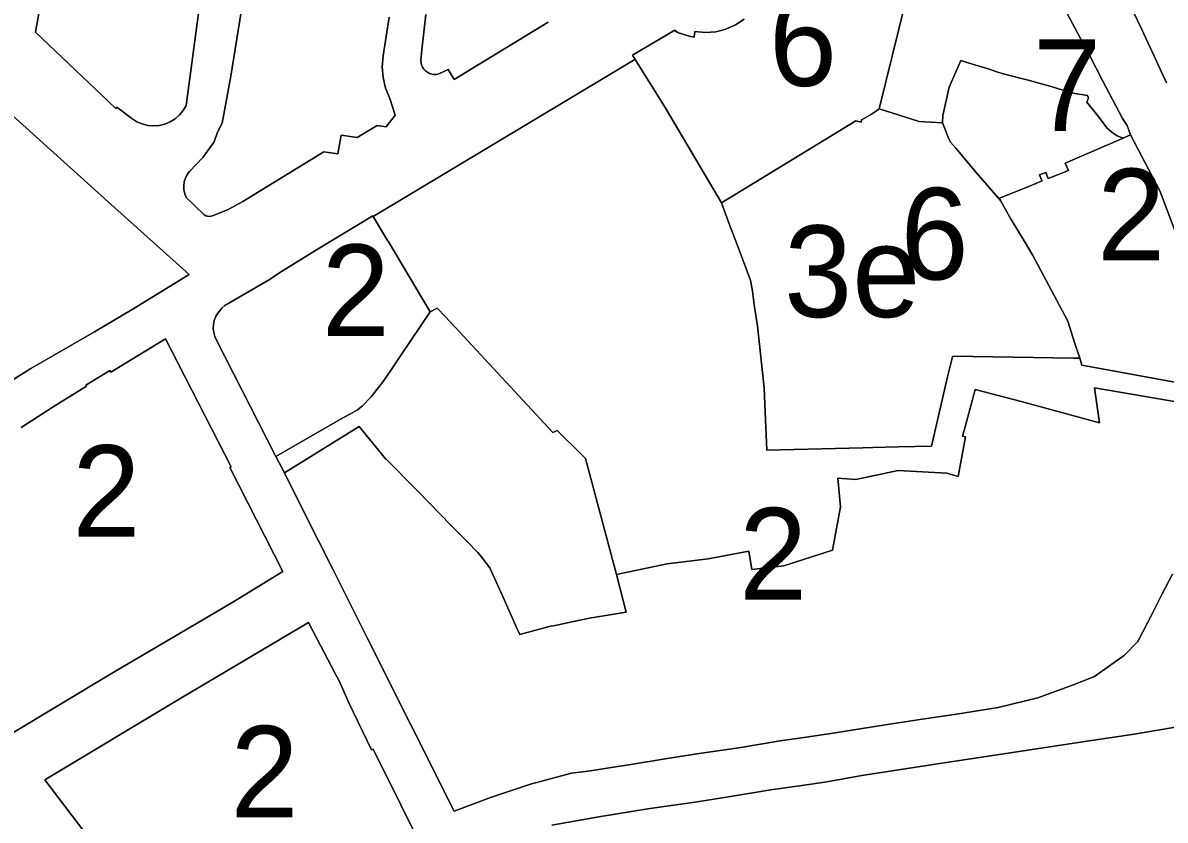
# Model space of a CAD drawing. Extents: x 598968 to 613553, y 4409678 to 4430833.
# Drawn here: x 607565.5 to 607715.2, y 4416375.4 to 4416479.9 of the extents above; entities that cross this region are included whole.
import ezdxf

# ---------------------------------------------------------------- set-up
doc = ezdxf.new("R2010")
doc.units = 0
for name, color, linetype in [('1', 7, 'Continuous'), ('SUBZONA 3e. EDIFICIS ENTRE MITGERES amb projecte especial', 7, 'Continuous'), ('ZONA 2. CARRERS DE CASES. Cases de trast', 7, 'Continuous'), ("ZONA 3. ILLES  D'EDIFICIS ENTRE MITGERES. EIXAMPLE.", 7, 'Continuous'), ('ZONA 6. EDIFICIS DE PISOS_ AÏLLATS I EN PARCEL.LES', 7, 'Continuous'), ('ZONA 7. CONJUNTS AMB ORDENACIONS ESPECÍFIQUES', 7, 'Continuous')]:
    doc.layers.add(name, color=color, linetype=linetype)

msp = doc.modelspace()

# ---------------------------------------------------------------- linework, layer by layer
at = {"layer": '1'}
for points in [[(607579.6918, 4416548.9945), (607584.0576, 4416548.2277), (607597.4675, 4416536.408), (607594.4076, 4416516.8082), (607589.6485, 4416489.6645), (607586.8878, 4416469.0585), (607586.5075, 4416468.4009), (607586.0264, 4416467.813), (607585.4571, 4416467.3101), (607584.8143, 4416466.9053), (607584.1149, 4416466.6092), (607583.3768, 4416466.4294), (607582.6195, 4416466.3705), (607581.8625, 4416466.4343), (607581.1257, 4416466.6189), (607580.4281, 4416466.9196), (607579.7879, 4416467.3284), (607577.8379, 4416468.8084), (607577.6879, 4416468.6584), (607567.168, 4416478.6381)], [(607643.3058, 4416407.559), (607643.2873, 4416407.5551), (607639.2425, 4416422.7691), (607638.7868, 4416423.2214), (607635.5472, 4416426.4367), (607634.9444, 4416426.1964), (607621.5759, 4416440.5814), (607621.5719, 4416440.5857), (607619.898, 4416442.3867), (607619.8075, 4416442.4843), (607618.897, 4416441.9936), (607615.0876, 4416436.3694), (607613.7882, 4416434.3877), (607612.7176, 4416432.8494), (607611.3071, 4416431.0654), (607611.1047, 4416430.8095), (607610.0244, 4416429.6742), (607609.3377, 4416429.1694), (607608.4427, 4416428.6494), (607607.5442, 4416428.1274), (607598.6578, 4416423.0393), (607599.7778, 4416420.9093), (607609.5877, 4416426.9494), (607613.0906, 4416422.6874), (607613.0993, 4416422.6777), (607617.2178, 4416418.5299), (607617.2972, 4416418.4493), (607621.5757, 4416414.0391), (607623.6294, 4416411.9724), (607625.1175, 4416410.4749), (607625.3833, 4416410.1381), (607626.7075, 4416408.4599), (607628.392, 4416404.6996), (607630.2444, 4416400.5217), (607630.6437, 4416399.6873), (607634.6675, 4416400.7902), (607635.0247, 4416400.8648), (607638.4943, 4416401.5887), (607639.9874, 4416401.9003), (607640.2815, 4416401.9484), (607644.5773, 4416402.6503), (607644.5756, 4416402.6569), (607643.2873, 4416407.5502), (607643.307, 4416407.5543)], [(607586.1981, 4416391.3494), (607602.9279, 4416401.2996), (607606.4778, 4416394.4898), (607606.9378, 4416393.6198), (607608.2878, 4416390.6798), (607611.1978, 4416384.58), (607611.4028, 4416384.67), (607615.0278, 4416377.3701), (607617.0677, 4416373.3102), (607613.2778, 4416371.2401), (607608.9179, 4416368.2401), (607604.578, 4416364.4601), (607604.738, 4416364.3401), (607601.618, 4416360.5301), (607601.408, 4416360.6401), (607595.9181, 4416350.1501), (607588.8482, 4416353.9399), (607579.0183, 4416366.6996), (607568.3783, 4416380.6393)]]:
    msp.add_lwpolyline(points, close=True, dxfattribs=at)
for points in [[(607613.5074, 4416480.6189), (607612.7174, 4416475.5589), (607612.6056, 4416474.1282), (607612.7143, 4416472.6973), (607613.0408, 4416471.2999), (607613.5775, 4416469.969), (607614.3075, 4416467.769), (607613.1175, 4416466.249), (607611.9175, 4416466.439), (607609.3176, 4416464.839), (607607.2176, 4416465.1689), (607606.7776, 4416462.689), (607604.9676, 4416462.9689), (607594.3478, 4416456.4488), (607592.4099, 4416455.4029), (607590.3678, 4416454.5788), (607590.1487, 4416454.5247), (607589.9236, 4416454.5087), (607589.699, 4416454.5314), (607589.4817, 4416454.592), (607589.2778, 4416454.6888), (607586.9079, 4416456.9787), (607586.7163, 4416457.4643), (607586.609, 4416457.9753), (607586.5891, 4416458.497), (607586.6571, 4416459.0146), (607586.8113, 4416459.5134), (607587.0471, 4416459.9792), (607587.3578, 4416460.3987), (607589.1122, 4416462.2167), (607590.5578, 4416464.2887), (607591.0277, 4416465.5299), (607591.6178, 4416466.7187), (607592.7577, 4416472.8886), (607595.282, 4416488.6863)], [(607548.7182, 4416481.6777), (607554.1282, 4416476.7379), (607561.4181, 4416470.1181), (607577.118, 4416456.0285), (607587.2779, 4416446.9088), (607579.838, 4416442.2987), (607574.8981, 4416439.3637), (607566.5582, 4416434.5486), (607561.4582, 4416431.3685), (607557.0483, 4416428.7685), (607554.4883, 4416427.3685), (607552.5284, 4416425.9884), (607539.7085, 4416418.2183), (607536.2286, 4416422.7782), (607526.8686, 4416434.8179), (607520.5687, 4416442.8477), (607518.9087, 4416444.9276), (607514.6887, 4416447.4175), (607511.0696, 4416448.9222), (607503.6483, 4416451.9927), (607496.0345, 4416454.9201), (607488.779, 4416458.087), (607477.7191, 4416462.8967)], [(607681.1705, 4416482.5814), (607677.7059, 4416468.596), (607682.9467, 4416466.9301), (607686.0266, 4416466.7603), (607686.0466, 4416467.7303), (607686.8966, 4416471.4303), (607688.4166, 4416474.9302), (607688.4263, 4416474.9273), (607690.0877, 4416474.4336), (607692.0165, 4416473.8603), (607693.1622, 4416473.4393), (607693.972, 4416473.1775), (607697.4065, 4416472.3304), (607698.8166, 4416471.936), (607699.9465, 4416471.6205), (607700.4067, 4416471.479), (607700.9414, 4416471.3255), (607702.9064, 4416470.7105), (607705.0464, 4416470.3306), (607705.1162, 4416470.1465), (607705.1564, 4416470.0406), (607704.9464, 4416469.4706), (607706.0395, 4416468.1186), (607706.3724, 4416467.6926), (607707.6064, 4416466.0807), (607708.2464, 4416465.5107), (607708.9264, 4416465.0807), (607709.7152, 4416464.7612), (607709.7876, 4416464.7933), (607710.6764, 4416465.2007), (607710.2336, 4416466.4073), (607709.6164, 4416467.3407), (607707.0114, 4416472.3156), (607705.2664, 4416475.6405), (607704.1033, 4416477.8153), (607703.3464, 4416479.2304), (607701.4264, 4416482.8204)], [(607701.4264, 4416482.8204), (607703.3464, 4416479.2304), (607704.1033, 4416477.8153), (607705.2664, 4416475.6405), (607707.0114, 4416472.3156), (607709.6164, 4416467.3407), (607710.2336, 4416466.4073), (607710.6764, 4416465.2007), (607714.4963, 4416457.8609), (607714.7278, 4416457.272), (607718.5863, 4416447.1111)], [(607715.38, 4416472.0059), (607713.7999, 4416475.428), (607712.1584, 4416478.9829), (607710.4133, 4416482.6275)], [(607710.4133, 4416482.6275), (607712.1584, 4416478.9829), (607713.7999, 4416475.428), (607715.38, 4416472.0059)], [(607716.1515, 4416407.6265), (607714.8315, 4416405.0215), (607713.5387, 4416402.5053), (607711.6266, 4416398.7815), (607709.8666, 4416396.9915), (607705.9367, 4416394.2215), (607703.0767, 4416393.0865), (607698.5367, 4416391.4214), (607693.3168, 4416390.1213), (607687.8669, 4416389.2812), (607683.3469, 4416388.6112), (607678.2384, 4416387.8405), (607671.3749, 4416386.7354), (607668.1471, 4416386.2559), (607664.7472, 4416385.7509), (607659.3172, 4416384.8708), (607654.1243, 4416384.0988), (607649.9373, 4416383.4406), (607644.9374, 4416382.6406), (607642.3574, 4416382.2405), (607639.9038, 4416381.8601), (607637.3975, 4416381.5204), (607632.0169, 4416380.0902), (607626.9165, 4416378.3742), (607622.0477, 4416376.5602), (607616.3277, 4416387.86), (607610.692, 4416399.0797), (607607.474, 4416405.5786), (607606.1578, 4416408.1896), (607604.2528, 4416411.985), (607602.3379, 4416415.8), (607599.7778, 4416420.9093), (607598.6578, 4416423.0393), (607590.8805, 4416438.266), (607590.6591, 4416438.7562), (607590.5176, 4416439.2751), (607590.4595, 4416439.8098), (607590.4863, 4416440.347), (607590.5973, 4416440.8733), (607590.7898, 4416441.3756), (607591.0589, 4416441.8413), (607591.3979, 4416442.2589), (607591.5654, 4416442.4564), (607591.9878, 4416442.8189), (607597.8978, 4416446.259), (607599.0577, 4416447.049), (607604.1977, 4416450.2491), (607611.3676, 4416454.5891), (607611.4178, 4416454.5042), (607645.7247, 4416475.0641), (607645.7423, 4416475.0719), (607645.3871, 4416475.6395), (607650.957, 4416478.9095), (607651.287, 4416478.6096), (607652.8417, 4416478.1042), (607653.487, 4416477.9996), (607653.567, 4416478.7296), (607654.9379, 4416478.5991), (607656.3111, 4416478.7032), (607657.6466, 4416479.0391), (607658.9059, 4416479.5967), (607660.0521, 4416480.36)], [(607634.3372, 4416479.9592), (607627.7373, 4416475.9492), (607622.0473, 4416472.4391), (607621.2274, 4416473.7591), (607620.0074, 4416473.1791), (607619.7042, 4416473.1214), (607619.3957, 4416473.1149), (607619.0904, 4416473.1596), (607618.7967, 4416473.2543), (607618.5228, 4416473.3964), (607618.2763, 4416473.5821), (607618.064, 4416473.8061), (607617.8918, 4416474.0622), (607617.7645, 4416474.3433), (607617.6857, 4416474.6417), (607617.6574, 4416474.949), (607617.8058, 4416476.3232), (607618.3074, 4416480.9689)], [(607565.2682, 4416426.8487), (607569.4781, 4416429.5287), (607573.8281, 4416432.2587), (607573.7481, 4416432.3987), (607576.888, 4416434.3188), (607577.018, 4416434.0988), (607584.1979, 4416438.4789), (607592.7879, 4416421.6892), (607592.6179, 4416421.5892), (607599.5679, 4416407.9695), (607593.0304, 4416403.9379), (607588.338, 4416401.2094), (607577.1382, 4416394.5892), (607563.7584, 4416386.5391)], [(607634.8075, 4416374.7205), (607641.0075, 4416375.8206), (607647.4274, 4416376.8407), (607653.8673, 4416377.7808), (607658.2273, 4416378.4708), (607663.5472, 4416379.3309), (607667.9071, 4416379.951), (607670.5871, 4416380.341), (607675.727, 4416381.2611), (607686.2269, 4416382.8813), (607699.5068, 4416384.9015), (607705.5367, 4416385.8261), (607711.1266, 4416386.6417), (607716.5566, 4416387.5518)]]:
    msp.add_lwpolyline(points, dxfattribs=at)
at = {"layer": 'SUBZONA 3e. EDIFICIS ENTRE MITGERES amb projecte especial'}
msp.add_lwpolyline([(607719.0835, 4416432.2823), (607704.2964, 4416435.0259), (607704.0071, 4416435.9043), (607704.0036, 4416435.9044), (607703.2148, 4416435.9169), (607687.3329, 4416436.169), (607687.3133, 4416436.085), (607686.7004, 4416433.4588), (607684.584, 4416424.3902), (607680.1917, 4416424.2846), (607676.8883, 4416424.2051), (607675.571, 4416424.1734), (607662.987, 4416423.8708), (607662.6672, 4416431.9553), (607662.6134, 4416432.4456), (607661.7651, 4416440.1463), (607661.3829, 4416442.6116), (607661.1041, 4416444.7068), (607660.877, 4416446.1301), (607659.0601, 4416450.8918), (607658.0708, 4416453.5397), (607657.047, 4416456.2799), (607655.507, 4416458.9399), (607649.687, 4416468.7696), (607645.7423, 4416475.0719), (607645.7247, 4416475.0641), (607611.4178, 4416454.5042), (607613.2984, 4416451.3584), (607613.3586, 4416451.2577), (607618.897, 4416441.9936), (607619.8075, 4416442.4843), (607619.898, 4416442.3867), (607621.5719, 4416440.5857), (607621.5759, 4416440.5814), (607634.9444, 4416426.1964), (607635.5472, 4416426.4367), (607638.7868, 4416423.2214), (607639.2425, 4416422.7691), (607643.2873, 4416407.5551), (607643.3058, 4416407.559), (607649.9572, 4416408.9552), (607655.3072, 4416409.6253), (607660.6271, 4416410.6254), (607661.0371, 4416408.2154), (607665.2171, 4416408.7155), (607671.587, 4416410.7456), (607672.667, 4416416.4256), (607672.307, 4416420.1955), (607674.6458, 4416420.0055), (607680.2169, 4416421.1856), (607686.6068, 4416420.8357), (607688.0968, 4416420.4358), (607689.0267, 4416425.5957), (607688.6565, 4416425.7002), (607688.9967, 4416426.9057), (607689.6567, 4416429.3657), (607690.3167, 4416431.8257), (607696.5266, 4416430.1858), (607706.5765, 4416427.446), (607705.9565, 4416432.026), (607718.9564, 4416429.7962)], dxfattribs=at)
at = {"layer": 'ZONA 2. CARRERS DE CASES. Cases de trast'}
for points in [[(607477.7191, 4416462.8967), (607488.779, 4416458.087), (607496.0345, 4416454.9201), (607503.6483, 4416451.9927), (607511.0696, 4416448.9222), (607514.6887, 4416447.4175), (607518.9087, 4416444.9276), (607520.5687, 4416442.8477), (607526.8686, 4416434.8179), (607536.2286, 4416422.7782), (607539.7085, 4416418.2183), (607552.5284, 4416425.9884), (607554.4883, 4416427.3685), (607557.0483, 4416428.7685), (607561.4582, 4416431.3685), (607566.5582, 4416434.5486), (607574.8981, 4416439.3637), (607579.838, 4416442.2987), (607587.2779, 4416446.9088), (607577.118, 4416456.0285), (607561.4181, 4416470.1181), (607554.1282, 4416476.7379), (607548.7182, 4416481.6777)], [(607718.5863, 4416447.1111), (607714.7278, 4416457.272), (607714.4963, 4416457.8609), (607710.6764, 4416465.2007), (607709.7876, 4416464.7933), (607709.7152, 4416464.7612), (607702.1178, 4416461.4912), (607702.5165, 4416460.5307), (607699.8565, 4416459.4506), (607699.5565, 4416460.2706), (607698.7565, 4416459.9306), (607699.0581, 4416459.1909), (607699.0665, 4416459.1706), (607697.4265, 4416458.4606), (607693.4273, 4416456.835), (607693.5366, 4416456.7105), (607693.6563, 4416456.4979), (607695.0166, 4416454.0806), (607696.7466, 4416451.2907), (607697.8512, 4416449.3917), (607702.4023, 4416440.8561), (607702.4838, 4416440.6635), (607703.2774, 4416438.0944), (607704.0036, 4416435.9044), (607704.0071, 4416435.9043), (607704.2964, 4416435.0259), (607719.0835, 4416432.2823)], [(607563.7584, 4416386.5391), (607577.1382, 4416394.5892), (607588.338, 4416401.2094), (607593.0304, 4416403.9379), (607599.5679, 4416407.9695), (607592.6179, 4416421.5892), (607592.7879, 4416421.6892), (607584.1979, 4416438.4789), (607577.018, 4416434.0988), (607576.888, 4416434.3188), (607573.7481, 4416432.3987), (607573.8281, 4416432.2587), (607569.4781, 4416429.5287), (607565.2682, 4416426.8487)], [(607718.9564, 4416429.7962), (607705.9565, 4416432.026), (607706.5765, 4416427.446), (607696.5266, 4416430.1858), (607690.3167, 4416431.8257), (607689.6567, 4416429.3657), (607688.9967, 4416426.9057), (607688.6565, 4416425.7002), (607689.0267, 4416425.5957), (607688.0968, 4416420.4358), (607686.6068, 4416420.8357), (607680.2169, 4416421.1856), (607674.6458, 4416420.0055), (607672.307, 4416420.1955), (607672.667, 4416416.4256), (607671.587, 4416410.7456), (607665.2171, 4416408.7155), (607661.0371, 4416408.2154), (607660.6271, 4416410.6254), (607655.3072, 4416409.6253), (607649.9572, 4416408.9552), (607643.3058, 4416407.559), (607643.307, 4416407.5543), (607643.2873, 4416407.5502), (607644.5756, 4416402.6569), (607644.5773, 4416402.6503), (607640.2815, 4416401.9484), (607639.9874, 4416401.9003), (607638.4943, 4416401.5887), (607635.0247, 4416400.8648), (607634.6675, 4416400.7902), (607630.6437, 4416399.6873), (607630.2444, 4416400.5217), (607628.392, 4416404.6996), (607626.7075, 4416408.4599), (607625.3833, 4416410.1381), (607625.1175, 4416410.4749), (607623.6294, 4416411.9724), (607621.5757, 4416414.0391), (607617.2972, 4416418.4493), (607617.2178, 4416418.5299), (607613.0993, 4416422.6777), (607613.0906, 4416422.6874), (607609.5877, 4416426.9494), (607599.7778, 4416420.9093), (607602.3379, 4416415.8), (607604.2528, 4416411.985), (607606.1578, 4416408.1896), (607607.474, 4416405.5786), (607610.692, 4416399.0797), (607616.3277, 4416387.86), (607622.0477, 4416376.5602), (607626.9165, 4416378.3742), (607632.0169, 4416380.0902), (607637.3975, 4416381.5204), (607639.9038, 4416381.8601), (607642.3574, 4416382.2405), (607644.9374, 4416382.6406), (607649.9373, 4416383.4406), (607654.1243, 4416384.0988), (607659.3172, 4416384.8708), (607664.7472, 4416385.7509), (607668.1471, 4416386.2559), (607671.3749, 4416386.7354), (607678.2384, 4416387.8405), (607683.3469, 4416388.6112), (607687.8669, 4416389.2812), (607693.3168, 4416390.1213), (607698.5367, 4416391.4214), (607703.0767, 4416393.0865), (607705.9367, 4416394.2215), (607709.8666, 4416396.9915), (607711.6266, 4416398.7815), (607713.5387, 4416402.5053), (607714.8315, 4416405.0215), (607716.1515, 4416407.6265)], [(607716.5566, 4416387.5518), (607711.1266, 4416386.6417), (607705.5367, 4416385.8261), (607699.5068, 4416384.9015), (607686.2269, 4416382.8813), (607675.727, 4416381.2611), (607670.5871, 4416380.341), (607667.9071, 4416379.951), (607663.5472, 4416379.3309), (607658.2273, 4416378.4708), (607653.8673, 4416377.7808), (607647.4274, 4416376.8407), (607641.0075, 4416375.8206), (607634.8075, 4416374.7205)]]:
    msp.add_lwpolyline(points, dxfattribs=at)
for points in [[(607611.4178, 4416454.5042), (607611.3676, 4416454.5891), (607604.1977, 4416450.2491), (607599.0577, 4416447.049), (607597.8978, 4416446.259), (607591.9878, 4416442.8189), (607591.5654, 4416442.4564), (607591.3979, 4416442.2589), (607591.0589, 4416441.8413), (607590.7898, 4416441.3756), (607590.5973, 4416440.8733), (607590.4863, 4416440.347), (607590.4595, 4416439.8098), (607590.5176, 4416439.2751), (607590.6591, 4416438.7562), (607590.8805, 4416438.266), (607598.6578, 4416423.0393), (607607.5442, 4416428.1274), (607608.4427, 4416428.6494), (607609.3377, 4416429.1694), (607610.0244, 4416429.6742), (607611.1047, 4416430.8095), (607611.3071, 4416431.0654), (607612.7176, 4416432.8494), (607613.7882, 4416434.3877), (607615.0876, 4416436.3694), (607618.897, 4416441.9936), (607613.3586, 4416451.2577), (607613.2984, 4416451.3584)], [(607608.2878, 4416390.6798), (607606.9378, 4416393.6198), (607606.4778, 4416394.4898), (607602.9279, 4416401.2996), (607586.1981, 4416391.3494), (607568.3783, 4416380.6393), (607579.0183, 4416366.6996), (607588.8482, 4416353.9399), (607595.9181, 4416350.1501), (607601.408, 4416360.6401), (607601.618, 4416360.5301), (607604.738, 4416364.3401), (607604.578, 4416364.4601), (607608.9179, 4416368.2401), (607613.2778, 4416371.2401), (607617.0677, 4416373.3102), (607615.0278, 4416377.3701), (607611.4028, 4416384.67), (607611.1978, 4416384.58)]]:
    msp.add_lwpolyline(points, close=True, dxfattribs=at)
at = {"layer": "ZONA 3. ILLES  D'EDIFICIS ENTRE MITGERES. EIXAMPLE."}
msp.add_lwpolyline([(607586.8878, 4416469.0585), (607589.6485, 4416489.6645), (607594.4076, 4416516.8082), (607597.4675, 4416536.408), (607584.0576, 4416548.2277), (607579.6918, 4416548.9945), (607567.168, 4416478.6381), (607577.6879, 4416468.6584), (607577.8379, 4416468.8084), (607579.7879, 4416467.3284), (607580.4281, 4416466.9196), (607581.1257, 4416466.6189), (607581.8625, 4416466.4343), (607582.6195, 4416466.3705), (607583.3768, 4416466.4294), (607584.1149, 4416466.6092), (607584.8143, 4416466.9053), (607585.4571, 4416467.3101), (607586.0264, 4416467.813), (607586.5075, 4416468.4009)], close=True, dxfattribs=at)
for points in [[(607595.282, 4416488.6863), (607592.7577, 4416472.8886), (607591.6178, 4416466.7187), (607591.0277, 4416465.5299), (607590.5578, 4416464.2887), (607589.1122, 4416462.2167), (607587.3578, 4416460.3987), (607587.0471, 4416459.9792), (607586.8113, 4416459.5134), (607586.6571, 4416459.0146), (607586.5891, 4416458.497), (607586.609, 4416457.9753), (607586.7163, 4416457.4643), (607586.9079, 4416456.9787), (607589.2778, 4416454.6888), (607589.4817, 4416454.592), (607589.699, 4416454.5314), (607589.9236, 4416454.5087), (607590.1487, 4416454.5247), (607590.3678, 4416454.5788), (607592.4099, 4416455.4029), (607594.3478, 4416456.4488), (607604.9676, 4416462.9689), (607606.7776, 4416462.689), (607607.2176, 4416465.1689), (607609.3176, 4416464.839), (607611.9175, 4416466.439), (607613.1175, 4416466.249), (607614.3075, 4416467.769), (607613.5775, 4416469.969), (607613.0408, 4416471.2999), (607612.7143, 4416472.6973), (607612.6056, 4416474.1282), (607612.7174, 4416475.5589), (607613.5074, 4416480.6189)], [(607618.3074, 4416480.9689), (607617.8058, 4416476.3232), (607617.6574, 4416474.949), (607617.6857, 4416474.6417), (607617.7645, 4416474.3433), (607617.8918, 4416474.0622), (607618.064, 4416473.8061), (607618.2763, 4416473.5821), (607618.5228, 4416473.3964), (607618.7967, 4416473.2543), (607619.0904, 4416473.1596), (607619.3957, 4416473.1149), (607619.7042, 4416473.1214), (607620.0074, 4416473.1791), (607621.2274, 4416473.7591), (607622.0473, 4416472.4391), (607627.7373, 4416475.9492), (607634.3372, 4416479.9592)]]:
    msp.add_lwpolyline(points, dxfattribs=at)
at = {"layer": 'ZONA 6. EDIFICIS DE PISOS_ AÏLLATS I EN PARCEL.LES'}
msp.add_lwpolyline([(607660.0521, 4416480.36), (607658.9059, 4416479.5967), (607657.6466, 4416479.0391), (607656.3111, 4416478.7032), (607654.9379, 4416478.5991), (607653.567, 4416478.7296), (607653.487, 4416477.9996), (607652.8417, 4416478.1042), (607651.287, 4416478.6096), (607650.957, 4416478.9095), (607645.3871, 4416475.6395), (607645.7423, 4416475.0719), (607649.687, 4416468.7696), (607655.507, 4416458.9399), (607657.047, 4416456.2799), (607666.5779, 4416462.0775), (607674.6868, 4416467.0101), (607675.3451, 4416466.8481), (607675.4268, 4416467.1801), (607676.5729, 4416467.8101), (607677.3588, 4416468.3547), (607677.6967, 4416468.5601), (607677.7004, 4416468.5751), (607677.7059, 4416468.596), (607681.1705, 4416482.5814)], dxfattribs=at)
msp.add_lwpolyline([(607686.0266, 4416466.7603), (607682.9467, 4416466.9301), (607677.7059, 4416468.596), (607677.7004, 4416468.5751), (607677.6967, 4416468.5601), (607677.3588, 4416468.3547), (607676.5729, 4416467.8101), (607675.4268, 4416467.1801), (607675.3451, 4416466.8481), (607674.6868, 4416467.0101), (607666.5779, 4416462.0775), (607657.047, 4416456.2799), (607658.0708, 4416453.5397), (607659.0601, 4416450.8918), (607660.877, 4416446.1301), (607661.1041, 4416444.7068), (607661.3829, 4416442.6116), (607661.7651, 4416440.1463), (607662.6134, 4416432.4456), (607662.6672, 4416431.9553), (607662.987, 4416423.8708), (607675.571, 4416424.1734), (607676.8883, 4416424.2051), (607680.1917, 4416424.2846), (607684.584, 4416424.3902), (607686.7004, 4416433.4588), (607687.3133, 4416436.085), (607687.3329, 4416436.169), (607703.2148, 4416435.9169), (607704.0036, 4416435.9044), (607703.2774, 4416438.0944), (607702.4838, 4416440.6635), (607702.4023, 4416440.8561), (607697.8512, 4416449.3917), (607696.7466, 4416451.2907), (607695.0166, 4416454.0806), (607693.6563, 4416456.4979), (607693.6066, 4416456.5793), (607690.4266, 4416460.2504), (607687.7501, 4416463.4309), (607687.0866, 4416464.2303), (607686.9476, 4416464.4933), (607686.8566, 4416464.6653)], close=True, dxfattribs=at)
at = {"layer": 'ZONA 7. CONJUNTS AMB ORDENACIONS ESPECÍFIQUES'}
msp.add_lwpolyline([(607709.7152, 4416464.7612), (607708.9264, 4416465.0807), (607708.2464, 4416465.5107), (607707.6064, 4416466.0807), (607706.3724, 4416467.6926), (607706.0395, 4416468.1186), (607704.9464, 4416469.4706), (607705.1564, 4416470.0406), (607705.1162, 4416470.1465), (607705.0464, 4416470.3306), (607702.9064, 4416470.7105), (607700.9414, 4416471.3255), (607700.4067, 4416471.479), (607699.9465, 4416471.6205), (607698.8166, 4416471.936), (607697.4065, 4416472.3304), (607693.972, 4416473.1775), (607693.1622, 4416473.4393), (607692.0165, 4416473.8603), (607690.0877, 4416474.4336), (607688.4263, 4416474.9273), (607688.4166, 4416474.9302), (607686.8966, 4416471.4303), (607686.0466, 4416467.7303), (607686.0266, 4416466.7603), (607686.8566, 4416464.6653), (607686.9476, 4416464.4933), (607687.0866, 4416464.2303), (607687.7501, 4416463.4309), (607690.4266, 4416460.2504), (607693.6066, 4416456.5793), (607693.6563, 4416456.4979), (607693.5366, 4416456.7105), (607693.4273, 4416456.835), (607697.4265, 4416458.4606), (607699.0665, 4416459.1706), (607699.0581, 4416459.1909), (607698.7565, 4416459.9306), (607699.5565, 4416460.2706), (607699.8565, 4416459.4506), (607702.5165, 4416460.5307), (607702.1178, 4416461.4912)], close=True, dxfattribs=at)

# ---------------------------------------------------------------- texts
at = {"layer": 'SUBZONA 3e. EDIFICIS ENTRE MITGERES amb projecte especial'}
msp.add_text('3e', height=12, dxfattribs=at).set_placement((607665.2671, 4416441.3135))
at = {"layer": 'ZONA 2. CARRERS DE CASES. Cases de trast'}
for p in [(607706.2973, 4416448.7415), (607604.6782, 4416438.8142), (607571.992, 4416412.509), (607659.3671, 4416404.2931), (607592.723, 4416375.7248)]:
    msp.add_text('2', height=12, dxfattribs=at).set_placement(p)
at = {"layer": 'ZONA 6. EDIFICIS DE PISOS_ AÏLLATS I EN PARCEL.LES'}
for p in [(607663.2788, 4416471.6093), (607680.5253, 4416446.2334)]:
    msp.add_text('6', height=12, dxfattribs=at).set_placement(p)
at = {"layer": 'ZONA 7. CONJUNTS AMB ORDENACIONS ESPECÍFIQUES'}
msp.add_text('7', height=12, dxfattribs=at).set_placement((607697.8709, 4416465.714))

doc.saveas('drawing.dxf')
